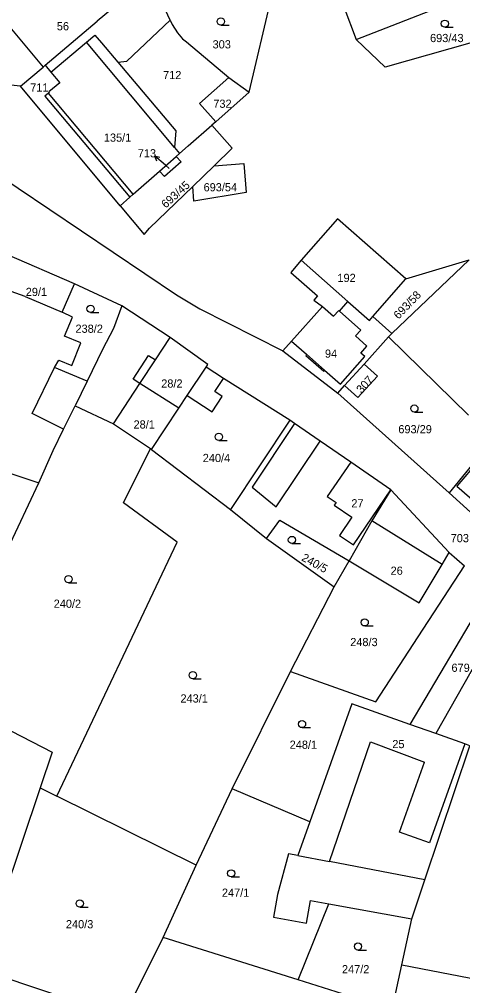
# Model space of a CAD drawing. Extents: x -7483133 to -743907, y -11317770 to -1129777.
# Drawn here: x -746496 to -746404, y -1132279.3 to -1132078.7 of the extents above; entities that cross this region are included whole.
import ezdxf

# ---------------------------------------------------------------- set-up
doc = ezdxf.new("R2010")
doc.units = 0
for name, color, linetype in [('Hranice parcel', 7, 'Continuous'), ('Parcelní čísla', 7, 'Continuous'), ('Pop  PČ popisy', 7, 'Continuous'), ('Vnitřní kresba', 7, 'Continuous'), ('Značky kultur', 7, 'Continuous')]:
    doc.layers.add(name, color=color, linetype=linetype)

msp = doc.modelspace()

# ---------------------------------------------------------------- linework, layer by layer
at = {"layer": 'Hranice parcel'}
for p, q in [((-746448.34, -1132093.81), (-746443.05, -1132071.26)), ((-746426.1, -1132082.89), (-746407.1, -1132075.5)), ((-746498.03, -1132080.35), (-746491.11, -1132088.59)), ((-746461.32, -1132083.39), (-746452.55, -1132090.79)), ((-746495.78, -1132092.58), (-746491.11, -1132088.59)), ((-746495.78, -1132092.58), (-746509.43, -1132091.08)), ((-746452.55, -1132090.79), (-746448.34, -1132093.81)), ((-746475.1, -1132117.39), (-746495.78, -1132092.58)), ((-746448.34, -1132093.81), (-746455.29, -1132099.94)), ((-746455.29, -1132099.94), (-746456.1, -1132100.64)), ((-746466.92, -1132110.18), (-746463.47, -1132107.14)), ((-746463.47, -1132107.14), (-746462.8, -1132106.55)), ((-746460.04, -1132113.37), (-746455.62, -1132109.09)), ((-746473.11, -1132115.64), (-746475.1, -1132117.39)), ((-746402.67, -1132128.64), (-746418.74, -1132143.92)), ((-746415.8, -1132132.54), (-746402.67, -1132128.64)), ((-746474.8, -1132138.2), (-746484.6, -1132133.59)), ((-746422.65, -1132140.36), (-746415.8, -1132132.54)), ((-746464.75, -1132144.73), (-746474.8, -1132138.2)), ((-746433.12, -1132138.33), (-746439.53, -1132145.49)), ((-746418.74, -1132143.92), (-746422.65, -1132140.36)), ((-746419.45, -1132144.58), (-746418.74, -1132143.92)), ((-746439.53, -1132145.49), (-746441.38, -1132147.52)), ((-746424.49, -1132150.27), (-746419.45, -1132144.58)), ((-746419.45, -1132144.58), (-746402.78, -1132160.86)), ((-746441.38, -1132147.52), (-746429.95, -1132156.33)), ((-746428.57, -1132154.69), (-746424.49, -1132150.27)), ((-746481.98, -1132153.82), (-746484.47, -1132158.9)), ((-746439.9, -1132161.92), (-746453.69, -1132153.29)), ((-746429.95, -1132156.33), (-746428.57, -1132154.69)), ((-746429.95, -1132156.33), (-746406.86, -1132176.98)), ((-746468.6, -1132167.97), (-746462.92, -1132159.41)), ((-746439.9, -1132161.92), (-746452.21, -1132180.46)), ((-746397.61, -1132165.68), (-746406.86, -1132176.98)), ((-746468.85, -1132167.8), (-746468.6, -1132167.97)), ((-746468.6, -1132167.97), (-746452.21, -1132180.46)), ((-746506.79, -1132206.34), (-746492.01, -1132174.94)), ((-746406.82, -1132189.39), (-746418.95, -1132176.36)), ((-746406.86, -1132176.98), (-746397.51, -1132185.52)), ((-746452.21, -1132180.46), (-746444.75, -1132186.48)), ((-746444.75, -1132186.48), (-746430.73, -1132196.48)), ((-746406.82, -1132189.39), (-746403.66, -1132192.14)), ((-746430.73, -1132196.48), (-746427.61, -1132191.08)), ((-746439.77, -1132214.12), (-746430.73, -1132196.48)), ((-746398.19, -1132196.61), (-746414.98, -1132225.06)), ((-746394.06, -1132199.47), (-746409.61, -1132226.97)), ((-746451.89, -1132238.47), (-746439.77, -1132214.12)), ((-746409.61, -1132226.97), (-746414.98, -1132225.06)), ((-746491.71, -1132238.23), (-746488.24, -1132239.95)), ((-746459.31, -1132254.28), (-746451.89, -1132238.47)), ((-746435.76, -1132245.3), (-746451.89, -1132238.47)), ((-746459.31, -1132254.28), (-746488.24, -1132239.95)), ((-746466.16, -1132269.31), (-746459.31, -1132254.28)), ((-746438.16, -1132278.12), (-746431.77, -1132262.32)), ((-746435.59, -1132261.62), (-746431.77, -1132262.32)), ((-746431.77, -1132262.32), (-746414.59, -1132265.47)), ((-746416.68, -1132275.01), (-746414.59, -1132265.47)), ((-746474.28, -1132285.54), (-746466.16, -1132269.31)), ((-746438.16, -1132278.12), (-746466.16, -1132269.31)), ((-746418.66, -1132284.23), (-746416.68, -1132275.01)), ((-746418.66, -1132284.23), (-746438.16, -1132278.12))]:
    msp.add_line(p, q, dxfattribs=at)
for points in [[(-746464.74, -1132078.87), (-746466.1, -1132075.88), (-746466.83, -1132073.88), (-746467.37, -1132071.81)], [(-746429.86, -1132074.04), (-746428.72, -1132076.1), (-746426.1, -1132082.89)], [(-746475.62, -1132087.56), (-746473.71, -1132087.35), (-746464.74, -1132078.87)], [(-746464.74, -1132078.87), (-746464.33, -1132079.76), (-746463.21, -1132081.52), (-746462.19, -1132082.72), (-746461.32, -1132083.39)], [(-746384.5, -1132078.54), (-746420.08, -1132088.64), (-746426.1, -1132082.89)], [(-746489.5, -1132089.65), (-746482.1, -1132083.45), (-746480.34, -1132081.97), (-746478.97, -1132083.6), (-746475.62, -1132087.56)], [(-746491.11, -1132088.59), (-746490.68, -1132088.23), (-746489.5, -1132089.65)], [(-746475.62, -1132087.56), (-746463.55, -1132101.86), (-746463.86, -1132105.28), (-746462.8, -1132106.55)], [(-746489.5, -1132089.65), (-746487.65, -1132091.87), (-746489.91, -1132093.76), (-746489.82, -1132093.88), (-746490.01, -1132094.04), (-746490.73, -1132094.66), (-746473.11, -1132115.64)], [(-746455.29, -1132099.94), (-746458.63, -1132096.15), (-746452.55, -1132090.79)], [(-746512.89, -1132094.09), (-746509.52, -1132104.89), (-746463.45, -1132135.88), (-746458.58, -1132138.82), (-746441.38, -1132147.52)], [(-746462.8, -1132106.55), (-746461.02, -1132104.98), (-746456.1, -1132100.64)], [(-746455.62, -1132109.09), (-746451.86, -1132105.45), (-746456.1, -1132100.64)], [(-746463.47, -1132107.14), (-746462.48, -1132108.27), (-746465.9, -1132111.34), (-746466.92, -1132110.18)], [(-746473.11, -1132115.64), (-746472.4, -1132115.01), (-746466.92, -1132110.18)], [(-746455.62, -1132109.09), (-746449.46, -1132108.64), (-746448.96, -1132114.63), (-746459.82, -1132116.44), (-746460.04, -1132113.37)], [(-746475.1, -1132117.39), (-746470.12, -1132123.36), (-746469.01, -1132122.04), (-746460.04, -1132113.37)], [(-746415.8, -1132132.54), (-746430, -1132120.09), (-746437.54, -1132128.72), (-746439.72, -1132131.22), (-746434.15, -1132136.09), (-746434.93, -1132136.99), (-746433.12, -1132138.33)], [(-746484.6, -1132133.59), (-746498.66, -1132127.5), (-746499.55, -1132129.55)], [(-746481.98, -1132153.82), (-746488.73, -1132150.99), (-746487.86, -1132149.42), (-746485.17, -1132150.55), (-746483.26, -1132145.87), (-746486.65, -1132144.48), (-746485, -1132140.49), (-746487.14, -1132139.46), (-746484.6, -1132133.59)], [(-746474.8, -1132138.2), (-746476.52, -1132142.87), (-746478.77, -1132147.26), (-746481.98, -1132153.82)], [(-746433.12, -1132138.33), (-746430.85, -1132140.35), (-746429.75, -1132139.12), (-746429.6, -1132139.26), (-746427.83, -1132137.27), (-746423.38, -1132141.19), (-746422.65, -1132140.36)], [(-746462.92, -1132159.41), (-746471.01, -1132154.29), (-746467.81, -1132149.4), (-746464.75, -1132144.73)], [(-746453.69, -1132153.29), (-746457.28, -1132150.91), (-746456.89, -1132150.33), (-746464.75, -1132144.73)], [(-746424.49, -1132150.27), (-746421.7, -1132152.74), (-746425.77, -1132157.17), (-746428.57, -1132154.69)], [(-746456.05, -1132160.19), (-746453.92, -1132156.98), (-746455.46, -1132155.96), (-746453.69, -1132153.29)], [(-746462.92, -1132159.41), (-746461.18, -1132156.79), (-746456.05, -1132160.19)], [(-746492.01, -1132174.94), (-746489.02, -1132168.19), (-746486.86, -1132163.77), (-746484.47, -1132158.9)], [(-746484.47, -1132158.9), (-746476.47, -1132162.64), (-746468.85, -1132167.8)], [(-746508.03, -1132161.18), (-746506.73, -1132161.88), (-746509.28, -1132169.18), (-746492.01, -1132174.94)], [(-746433.6, -1132166.24), (-746438.91, -1132162.6), (-746439.9, -1132161.92)], [(-746418.95, -1132176.36), (-746427.27, -1132170.61), (-746433.6, -1132166.24)], [(-746488.24, -1132239.95), (-746463.28, -1132187.24), (-746474.43, -1132179.05), (-746468.85, -1132167.8)], [(-746418.95, -1132176.36), (-746422.87, -1132182.82), (-746427.61, -1132191.08)], [(-746444.75, -1132186.48), (-746441.98, -1132182.67), (-746427.61, -1132191.08)], [(-746427.61, -1132191.08), (-746413.07, -1132199.82), (-746408.27, -1132191.87), (-746406.82, -1132189.39)], [(-746439.77, -1132214.12), (-746422.02, -1132220.4), (-746413.23, -1132206.88), (-746403.66, -1132192.14)], [(-746512.76, -1132218.71), (-746489.23, -1132230.86), (-746491.71, -1132238.23)], [(-746414.98, -1132225.06), (-746427.06, -1132220.77), (-746435.76, -1132245.3)], [(-746402.53, -1132229.49), (-746403.57, -1132229.12), (-746409.61, -1132226.97)], [(-746414.59, -1132265.47), (-746411.87, -1132257.36), (-746402.53, -1132229.49)], [(-746491.71, -1132238.23), (-746503.25, -1132272.52), (-746504.41, -1132275.72)], [(-746435.76, -1132245.3), (-746438.24, -1132252.29), (-746440.19, -1132251.91), (-746442.43, -1132260.37), (-746443.3, -1132265.09)], [(-746443.3, -1132265.09), (-746436.46, -1132266.34), (-746435.59, -1132261.62)], [(-746416.68, -1132275.01), (-746400.51, -1132278.11), (-746398.85, -1132274.79)], [(-746485.44, -1132282.28), (-746499.8, -1132277.41), (-746504.41, -1132275.72)]]:
    msp.add_lwpolyline(points, dxfattribs=at)
at = {"layer": 'Pop  PČ popisy'}
for p, q in [((-746465.7, -1132108.98), (-746467.96, -1132107.01)), ((-746467.96, -1132107.01), (-746466.88, -1132107.29)), ((-746467.96, -1132107.01), (-746467.54, -1132108.05)), ((-746464.95, -1132109.64), (-746465.7, -1132108.98))]:
    msp.add_line(p, q, dxfattribs=at)
at = {"layer": 'Vnitřní kresba'}
for p, q in [((-746475.14, -1132075.1), (-746479.87, -1132079.1)), ((-746490.68, -1132088.23), (-746479.87, -1132079.1)), ((-746463.86, -1132105.28), (-746482.1, -1132083.45)), ((-746472.4, -1132115.01), (-746490.01, -1132094.04)), ((-746437.54, -1132128.72), (-746427.83, -1132137.27)), ((-746494.82, -1132136.26), (-746497.76, -1132135.18)), ((-746494.82, -1132136.26), (-746487.14, -1132139.46)), ((-746429.6, -1132139.26), (-746425.18, -1132143.19)), ((-746425.18, -1132143.19), (-746426.28, -1132144.42)), ((-746426.28, -1132144.42), (-746423.89, -1132146.55)), ((-746439.53, -1132145.49), (-746436.41, -1132148.24)), ((-746436.41, -1132148.24), (-746436.59, -1132148.45)), ((-746436.59, -1132148.45), (-746432.87, -1132151.74)), ((-746432.68, -1132151.53), (-746436.41, -1132148.24)), ((-746425.15, -1132147.97), (-746423.89, -1132146.55)), ((-746424.32, -1132148.7), (-746425.15, -1132147.97)), ((-746472.4, -1132153.39), (-746469.22, -1132148.47)), ((-746469.22, -1132148.47), (-746467.81, -1132149.4)), ((-746429.39, -1132154.44), (-746424.32, -1132148.7)), ((-746493.39, -1132160.49), (-746488.73, -1132150.99)), ((-746461.18, -1132156.79), (-746457.28, -1132150.91)), ((-746432.87, -1132151.74), (-746432.68, -1132151.53)), ((-746432.68, -1132151.53), (-746429.39, -1132154.44)), ((-746476.47, -1132162.64), (-746471.01, -1132154.29)), ((-746471.01, -1132154.29), (-746472.4, -1132153.39)), ((-746486.86, -1132163.77), (-746493.39, -1132160.49)), ((-746438.91, -1132162.6), (-746447.75, -1132175.82)), ((-746442.73, -1132179.87), (-746433.6, -1132166.24)), ((-746400.72, -1132170.37), (-746405.23, -1132175.59)), ((-746447.75, -1132175.82), (-746442.73, -1132179.87)), ((-746405.23, -1132175.59), (-746395.9, -1132183.77)), ((-746408.27, -1132191.87), (-746422.87, -1132182.82)), ((-746431.66, -1132253.55), (-746423.15, -1132228.66)), ((-746423.15, -1132228.66), (-746411.94, -1132232.94)), ((-746403.57, -1132229.12), (-746410.88, -1132249.69)), ((-746417.11, -1132247.47), (-746411.94, -1132232.94)), ((-746410.88, -1132249.69), (-746417.11, -1132247.47)), ((-746438.24, -1132252.29), (-746431.66, -1132253.55)), ((-746411.87, -1132257.36), (-746431.66, -1132253.55))]:
    msp.add_line(p, q, dxfattribs=at)
msp.add_lwpolyline([(-746427.27, -1132170.61), (-746432.16, -1132177.73), (-746430.31, -1132178.99), (-746430.7, -1132179.57), (-746427.03, -1132182.07), (-746429.6, -1132185.84), (-746426.7, -1132187.81), (-746418.95, -1132176.36)], dxfattribs=at)
at = {"layer": 'Značky kultur'}
for p, q in [((-746454.23, -1132079.89), (-746452.48, -1132079.89)), ((-746407.73, -1132080.34), (-746405.98, -1132080.34)), ((-746481.26, -1132139.54), (-746479.51, -1132139.54)), ((-746414.05, -1132160.25), (-746412.3, -1132160.25)), ((-746454.64, -1132166.12), (-746452.89, -1132166.12)), ((-746439.46, -1132187.53), (-746437.71, -1132187.53)), ((-746485.83, -1132195.67), (-746484.08, -1132195.67)), ((-746424.36, -1132204.64), (-746422.61, -1132204.64)), ((-746460.03, -1132215.6), (-746458.28, -1132215.6)), ((-746437.37, -1132225.74), (-746435.62, -1132225.74)), ((-746452.08, -1132256.74), (-746450.33, -1132256.74)), ((-746483.5, -1132263.01), (-746481.75, -1132263.01)), ((-746425.75, -1132271.91), (-746424, -1132271.91))]:
    msp.add_line(p, q, dxfattribs=at)
for centre in [(-746454.23, -1132079.14), (-746407.73, -1132079.59), (-746481.26, -1132138.79), (-746414.05, -1132159.5), (-746454.64, -1132165.37), (-746439.46, -1132186.78), (-746485.83, -1132194.92), (-746424.36, -1132203.89), (-746460.03, -1132214.85), (-746437.37, -1132224.99), (-746452.08, -1132255.99), (-746483.5, -1132262.26), (-746425.75, -1132271.16)]:
    msp.add_circle(centre, 0.75, dxfattribs=at)

# ---------------------------------------------------------------- texts
at = {"layer": 'Parcelní čísla'}
for s, p in [('56', (-746488.26, -1132080.97)), ('693/43', (-746410.79, -1132083.42)), ('303', (-746455.93, -1132084.73)), ('712', (-746466.21, -1132091.11)), ('711', (-746493.78, -1132093.69)), ('732', (-746455.78, -1132097.06)), ('135/1', (-746478.5, -1132104.1)), ('713', (-746471.46, -1132107.35)), ('693/54', (-746457.8, -1132114.4)), ('192', (-746430.02, -1132133.22)), ('29/1', (-746494.71, -1132136.13)), ('238/2', (-746484.39, -1132143.77)), ('94', (-746432.61, -1132148.94)), ('28/2', (-746466.59, -1132155.15)), ('28/1', (-746472.34, -1132163.65)), ('693/29', (-746417.38, -1132164.63)), ('240/4', (-746457.97, -1132170.61)), ('27', (-746427.13, -1132180.02)), ('703', (-746406.52, -1132187.25)), ('26', (-746418.99, -1132194.01)), ('240/2', (-746488.91, -1132200.86)), ('248/3', (-746427.36, -1132208.82)), ('679', (-746406.35, -1132214.16)), ('243/1', (-746462.6, -1132220.53)), ('248/1', (-746439.93, -1132230.13)), ('25', (-746418.63, -1132230)), ('247/1', (-746454, -1132260.85)), ('240/3', (-746486.38, -1132267.4)), ('247/2', (-746429.08, -1132276.75))]:
    msp.add_text(s, height=1.7, dxfattribs=at).set_placement(p)
for s, rotation, p in [('693/45', 42, (-746465.65, -1132118)), ('693/58', 46, (-746417.34, -1132141.06)), ('307', 47, (-746425.04, -1132156.47)), ('240/5', 331, (-746437.62, -1132190.95))]:
    msp.add_text(s, height=1.7, rotation=rotation, dxfattribs=at).set_placement(p)

doc.saveas('drawing.dxf')
